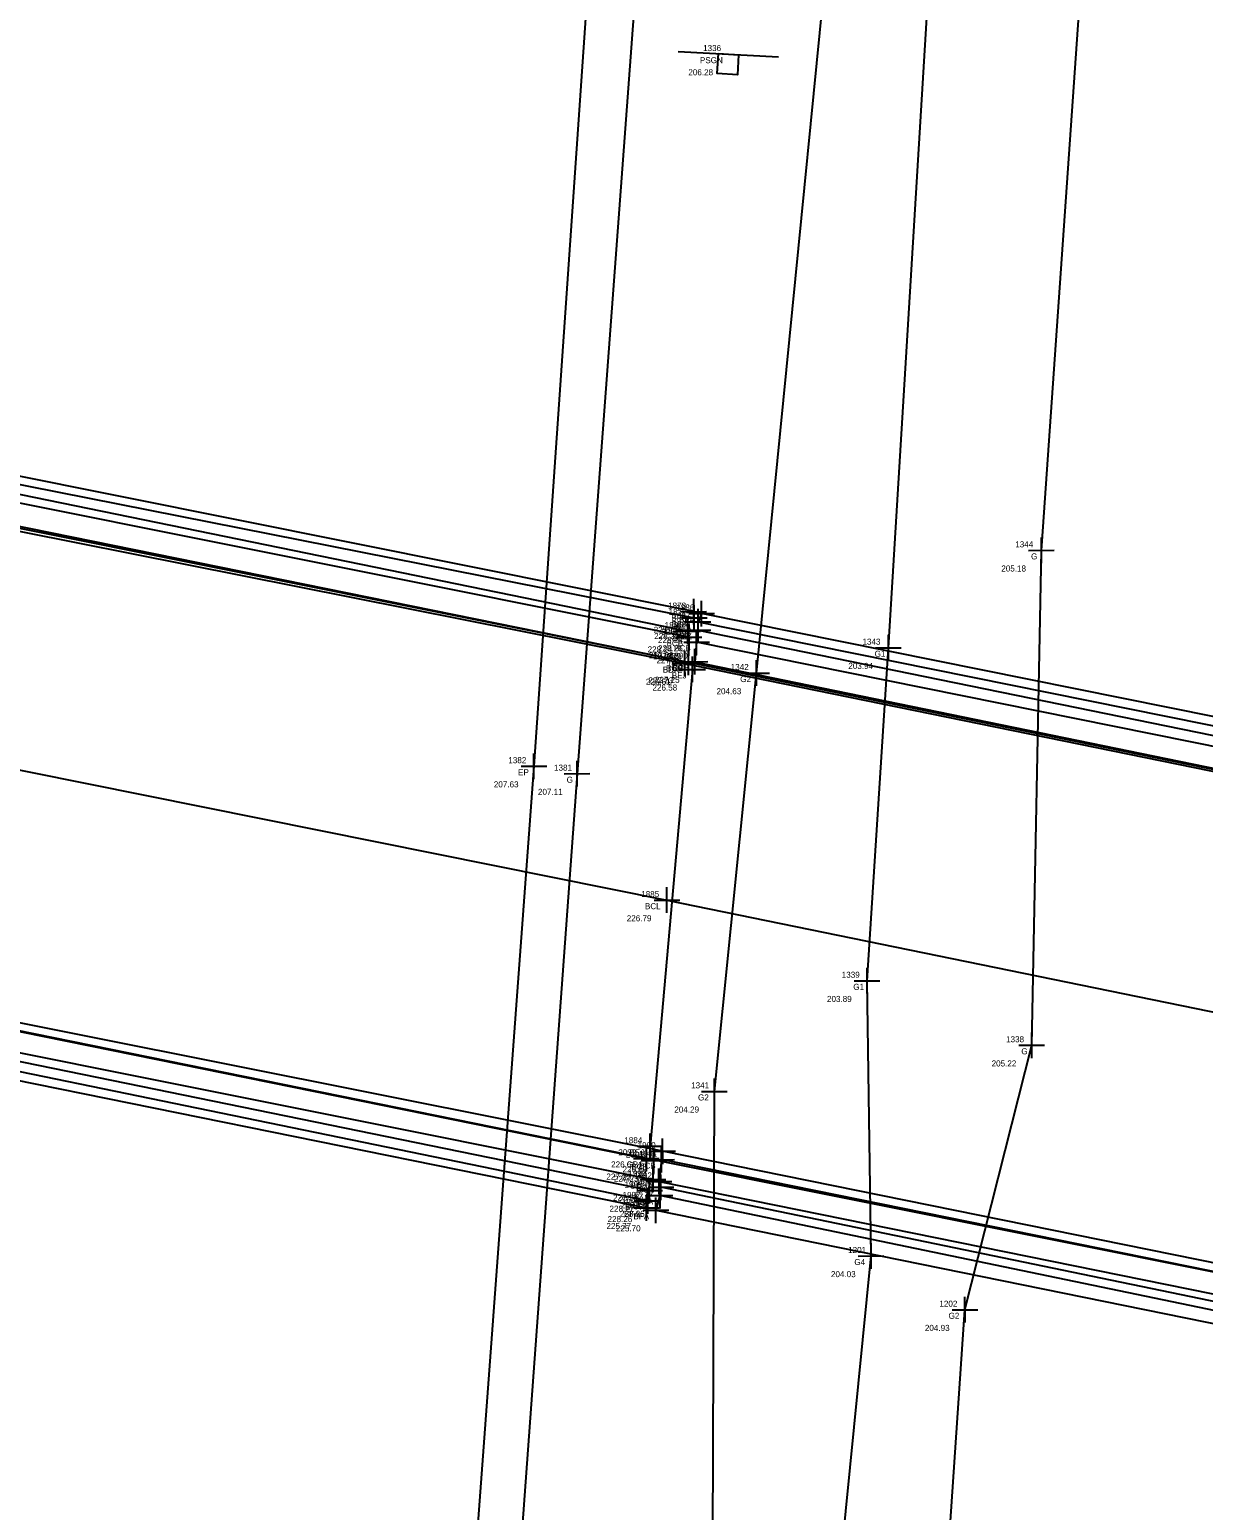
# Model space of a CAD drawing. Extents: x 1158983 to 1160032, y 610902 to 611573.
# Drawn here: x 1159401 to 1159459.3, y 611227.2 to 611300.7 of the extents above; entities that cross this region are included whole.
import ezdxf

# ---------------------------------------------------------------- set-up
doc = ezdxf.new("R2010")
doc.units = 0
for name, color, linetype in [('Default', 7, 'Continuous'), ('S_Bridge_Centerline', 7, 'Continuous'), ('S_Bridge_Curb', 7, 'Continuous'), ('S_Bridge_Deck', 7, 'Continuous'), ('S_Bridge_ExpansionJoint', 7, 'Continuous'), ('S_Bridge_Fascia', 7, 'Continuous'), ('S_Field_Code', 7, 'Continuous'), ('S_Ground_Elevation', 7, 'Continuous'), ('S_Guardrail_Beam', 7, 'Continuous'), ('S_Misc_MiscFeature', 7, 'Continuous'), ('S_Point_Elevation', 7, 'Continuous'), ('S_Point_Name', 7, 'Continuous'), ('S_Roadway_Edge_Pavement', 7, 'Continuous'), ('S_Survey_Shot', 7, 'Continuous'), ('S_Traffic_Sign_SinglePost', 7, 'Continuous')]:
    doc.layers.add(name, color=color, linetype=linetype)

msp = doc.modelspace()

# ---------------------------------------------------------------- linework, layer by layer
at = {"layer": 'Default'}
msp.add_line((1159435.703, 611299.476), (1159435.703, 611299.476), dxfattribs=at)
at = {"layer": 'S_Bridge_Centerline'}
msp.add_lwpolyline([(1159333.27, 611277.49), (1159375.085, 611269.079), (1159432.648, 611257.515), (1159502.769, 611243.159), (1159572.889, 611228.86), (1159630.259, 611216.999), (1159672.294, 611208.379)], dxfattribs=at)
at = {"layer": 'S_Bridge_Curb'}
for points in [[(1159376.749, 611281.964), (1159376.649, 611280.913), (1159433.724, 611269.316), (1159433.747, 611270.559)], [(1159434.12, 611270.309), (1159434.043, 611269.342), (1159503.64, 611255.058), (1159503.943, 611256.229)], [(1159431.968, 611243.66), (1159432.006, 611244.597), (1159374.882, 611256.199), (1159374.713, 611255.117)], [(1159502.019, 611229.4), (1159502.097, 611230.494), (1159432.384, 611244.643), (1159432.259, 611243.563)]]:
    msp.add_lwpolyline(points, close=True, dxfattribs=at)
at = {"layer": 'S_Bridge_Deck'}
msp.add_lwpolyline([(1159333.801, 611289.348), (1159375.965, 611280.699), (1159433.546, 611269.247), (1159503.551, 611254.972), (1159573.652, 611240.691), (1159630.945, 611229.008), (1159674.004, 611220.503), (1159672.341, 611196.28), (1159630.068, 611204.797), (1159572.75, 611216.514), (1159502.493, 611230.859), (1159432.439, 611245.062), (1159375.072, 611256.503), (1159331.888, 611265.329)], close=True, dxfattribs=at)
at = {"layer": 'S_Bridge_ExpansionJoint'}
msp.add_lwpolyline([(1159433.923, 611268.959), (1159431.823, 611245.308)], dxfattribs=at)
at = {"layer": 'S_Bridge_Fascia'}
for points in [[(1159377.015, 611283.251), (1159376.893, 611282.801), (1159434.008, 611271.511), (1159433.985, 611271.823)], [(1159434.373, 611271.73), (1159434.201, 611271.323), (1159503.969, 611257.243), (1159503.98, 611257.715)], [(1159431.641, 611242.253), (1159431.696, 611242.594), (1159374.735, 611254.312), (1159374.563, 611253.824)], [(1159501.804, 611227.968), (1159501.921, 611228.418), (1159432.308, 611242.862), (1159432.108, 611242.134)]]:
    msp.add_lwpolyline(points, close=True, dxfattribs=at)
at = {"layer": 'S_Ground_Elevation'}
for points in [[(1159454.139, 611570.997), (1159458.202, 611562.09), (1159457.609, 611547.211), (1159454.619, 611542.487), (1159450.49, 611533.823), (1159446.117, 611504.156), (1159442.895, 611458.608), (1159439.042, 611406.131), (1159435.384, 611353.576), (1159431.022, 611301.793), (1159428.193, 611263.786), (1159425.306, 611224.13), (1159422.825, 611193.921)], [(1159442.58, 611253.515), (1159443.638, 611270.034), (1159446.663, 611319.797), (1159445.969, 611361.1), (1159452.096, 611434.206), (1159455.542, 611485.465), (1159457.112, 611517.478), (1159459.746, 611531.666), (1159467.247, 611556.821), (1159464.351, 611565.449)], [(1159450.746, 611250.316), (1159451.228, 611274.864), (1159454.464, 611321.083), (1159460.98, 611368.506), (1159466.572, 611431.188), (1159472.814, 611485.778), (1159480.719, 611532.131), (1159483.428, 611564.473)], [(1159435.008, 611248.029), (1159437.102, 611268.779), (1159442.169, 611320.104)], [(1159442.777, 611239.865), (1159442.58, 611253.515)], [(1159447.437, 611237.199), (1159450.746, 611250.316)], [(1159434.908, 611221.492), (1159435.008, 611248.029)], [(1159548.979, 611025.788), (1159542.436, 611014.266), (1159539.927, 611011.357), (1159531.238, 611011.839), (1159506.951, 611012.56), (1159474.729, 611015.393), (1159451.448, 611016.781), (1159439.176, 611019.336), (1159436.035, 611022.533), (1159431.749, 611036.179), (1159430.572, 611089.92), (1159433.994, 611135.997), (1159437.548, 611187.051), (1159442.777, 611239.865)], [(1159563.258, 611229.802), (1159560.327, 611199.972), (1159558.111, 611173.246), (1159552.181, 611112.175), (1159547.04, 611094.195), (1159543.95, 611063.057), (1159534.181, 611016.708), (1159531.65, 611015.253), (1159507.988, 611014.741), (1159475.963, 611018.062), (1159451.464, 611020.697), (1159444.921, 611021.818), (1159442.672, 611026.506), (1159440.129, 611032.942), (1159436.622, 611046.038), (1159436.543, 611063.181), (1159435.008, 611090.376), (1159437.46, 611138.138), (1159443.944, 611185.758), (1159447.437, 611237.199)]]:
    msp.add_lwpolyline(points, dxfattribs=at)
at = {"layer": 'S_Guardrail_Beam'}
for p, q in [((1159375.839, 611280.908), (1159433.724, 611269.316)), ((1159433.724, 611269.316), (1159503.64, 611255.058))]:
    msp.add_line(p, q, dxfattribs=at)
msp.add_lwpolyline([(1159962.355, 611128.723), (1159954.927, 611131.331), (1159940.804, 611136.335), (1159922.846, 611140.981), (1159878.137, 611150.269), (1159824.181, 611161.329), (1159771.192, 611171.967), (1159724.558, 611182.82), (1159696.585, 611190.71), (1159683.564, 611193.82), (1159671.877, 611196.264), (1159629.625, 611204.61), (1159571.633, 611216.492), (1159501.577, 611230.682), (1159431.638, 611244.705), (1159374.182, 611256.374), (1159332.105, 611265.121)], dxfattribs=at)
at = {"layer": 'S_Misc_MiscFeature'}
for points in [[(1159376.941, 611282.479), (1159433.683, 611270.853)], [(1159434.199, 611270.905), (1159503.923, 611256.66)], [(1159431.791, 611243.111), (1159374.79, 611254.764)], [(1159501.916, 611228.898), (1159432.353, 611243.274)]]:
    msp.add_lwpolyline(points, dxfattribs=at)
at = {"layer": 'S_Roadway_Edge_Pavement'}
msp.add_lwpolyline([(1159451.831, 611570.814), (1159453.615, 611550.243), (1159453.735, 611546.55), (1159452.377, 611543.751), (1159448.762, 611533.854), (1159446.196, 611521.649), (1159443.913, 611504.847), (1159440.366, 611457.527), (1159436.414, 611406.688), (1159432.596, 611353.772), (1159428.66, 611301.968), (1159426.055, 611264.157), (1159423.109, 611224.366), (1159421.227, 611195.325), (1159419.39, 611189.09)], dxfattribs=at)
at = {"layer": 'S_Survey_Shot'}
for p, q in [((1159450.592, 611274.863), (1159451.864, 611274.866)), ((1159451.229, 611274.228), (1159451.227, 611275.501)), ((1159451.228, 611274.864), (1159451.228, 611274.864)), ((1159433.986, 611271.187), (1159433.984, 611272.459)), ((1159434.009, 611270.875), (1159434.006, 611272.148)), ((1159434.202, 611270.687), (1159434.199, 611271.96)), ((1159434.374, 611271.093), (1159434.371, 611272.366)), ((1159433.349, 611271.822), (1159434.621, 611271.824)), ((1159433.371, 611271.51), (1159434.644, 611271.513)), ((1159433.564, 611271.322), (1159434.837, 611271.325)), ((1159433.685, 611270.217), (1159433.682, 611271.49)), ((1159433.737, 611271.728), (1159435.009, 611271.731)), ((1159433.748, 611269.922), (1159433.745, 611271.195)), ((1159433.985, 611271.823), (1159433.985, 611271.823)), ((1159434.008, 611271.511), (1159434.008, 611271.511)), ((1159434.201, 611270.269), (1159434.198, 611271.541)), ((1159434.201, 611271.323), (1159434.201, 611271.323)), ((1159434.373, 611271.73), (1159434.373, 611271.73)), ((1159433.047, 611270.852), (1159434.32, 611270.855)), ((1159433.11, 611270.557), (1159434.383, 611270.56)), ((1159433.563, 611270.903), (1159434.836, 611270.906)), ((1159433.683, 611270.853), (1159433.683, 611270.853)), ((1159433.747, 611270.559), (1159433.747, 611270.559)), ((1159434.122, 611269.672), (1159434.119, 611270.945)), ((1159434.199, 611270.905), (1159434.199, 611270.905)), ((1159443.639, 611269.398), (1159443.636, 611270.671)), ((1159433.484, 611270.307), (1159434.757, 611270.31)), ((1159433.547, 611268.611), (1159433.545, 611269.883)), ((1159433.726, 611268.679), (1159433.723, 611269.952)), ((1159433.726, 611268.679), (1159433.723, 611269.952)), ((1159434.044, 611268.706), (1159434.041, 611269.978)), ((1159434.12, 611270.309), (1159434.12, 611270.309)), ((1159443.002, 611270.033), (1159444.274, 611270.036)), ((1159443.638, 611270.034), (1159443.638, 611270.034)), ((1159432.91, 611269.245), (1159434.182, 611269.248)), ((1159433.088, 611269.314), (1159434.36, 611269.317)), ((1159433.088, 611269.314), (1159434.36, 611269.317)), ((1159433.287, 611268.958), (1159434.559, 611268.961)), ((1159433.406, 611269.341), (1159434.679, 611269.343)), ((1159433.546, 611269.247), (1159433.546, 611269.247)), ((1159433.724, 611269.316), (1159433.724, 611269.316)), ((1159433.724, 611269.316), (1159433.724, 611269.316)), ((1159433.924, 611268.323), (1159433.922, 611269.596)), ((1159433.923, 611268.959), (1159433.923, 611268.959)), ((1159434.043, 611269.342), (1159434.043, 611269.342)), ((1159437.103, 611268.143), (1159437.1, 611269.415)), ((1159436.466, 611268.778), (1159437.738, 611268.78)), ((1159437.102, 611268.779), (1159437.102, 611268.779)), ((1159426.056, 611263.521), (1159426.054, 611264.793)), ((1159425.419, 611264.156), (1159426.691, 611264.158)), ((1159426.055, 611264.157), (1159426.055, 611264.157)), ((1159428.195, 611263.15), (1159428.192, 611264.423)), ((1159427.557, 611263.785), (1159428.83, 611263.788)), ((1159428.193, 611263.786), (1159428.193, 611263.786)), ((1159432.649, 611256.878), (1159432.647, 611258.151)), ((1159432.012, 611257.513), (1159433.284, 611257.516)), ((1159432.648, 611257.515), (1159432.648, 611257.515)), ((1159442.581, 611252.879), (1159442.579, 611254.151)), ((1159441.944, 611253.513), (1159443.216, 611253.516)), ((1159442.58, 611253.515), (1159442.58, 611253.515)), ((1159450.748, 611249.68), (1159450.745, 611250.952)), ((1159450.11, 611250.315), (1159451.383, 611250.317)), ((1159450.746, 611250.316), (1159450.746, 611250.316)), ((1159435.009, 611247.393), (1159435.006, 611248.666)), ((1159434.372, 611248.028), (1159435.644, 611248.031)), ((1159435.008, 611248.029), (1159435.008, 611248.029)), ((1159431.824, 611244.672), (1159431.822, 611245.944)), ((1159432.441, 611244.426), (1159432.438, 611245.699)), ((1159431.187, 611245.307), (1159432.459, 611245.309)), ((1159431.639, 611244.069), (1159431.636, 611245.341)), ((1159431.803, 611245.061), (1159433.076, 611245.064)), ((1159431.823, 611245.308), (1159431.823, 611245.308)), ((1159432.007, 611243.961), (1159432.004, 611245.233)), ((1159432.386, 611244.007), (1159432.383, 611245.279)), ((1159432.439, 611245.062), (1159432.439, 611245.062)), ((1159431.002, 611244.704), (1159432.274, 611244.707)), ((1159431.37, 611244.596), (1159432.642, 611244.598)), ((1159431.638, 611244.705), (1159431.638, 611244.705)), ((1159431.748, 611244.642), (1159433.02, 611244.644)), ((1159431.97, 611243.024), (1159431.967, 611244.296)), ((1159432.006, 611244.597), (1159432.006, 611244.597)), ((1159432.261, 611242.927), (1159432.258, 611244.2)), ((1159432.384, 611244.643), (1159432.384, 611244.643)), ((1159431.332, 611243.659), (1159432.605, 611243.661)), ((1159431.623, 611243.562), (1159432.896, 611243.565)), ((1159431.717, 611243.273), (1159432.989, 611243.275)), ((1159431.793, 611242.475), (1159431.79, 611243.747)), ((1159431.968, 611243.66), (1159431.968, 611243.66)), ((1159432.259, 611243.563), (1159432.259, 611243.563)), ((1159432.31, 611242.226), (1159432.307, 611243.498)), ((1159432.354, 611242.638), (1159432.351, 611243.91)), ((1159432.353, 611243.274), (1159432.353, 611243.274)), ((1159431.06, 611242.593), (1159432.332, 611242.596)), ((1159431.155, 611243.11), (1159432.428, 611243.112)), ((1159431.642, 611241.617), (1159431.64, 611242.889)), ((1159431.672, 611242.86), (1159432.945, 611242.863)), ((1159431.698, 611241.958), (1159431.695, 611243.231)), ((1159431.696, 611242.594), (1159431.696, 611242.594)), ((1159431.791, 611243.111), (1159431.791, 611243.111)), ((1159432.11, 611241.498), (1159432.107, 611242.77)), ((1159432.308, 611242.862), (1159432.308, 611242.862)), ((1159431.005, 611242.252), (1159432.277, 611242.254)), ((1159431.472, 611242.133), (1159432.745, 611242.135)), ((1159431.641, 611242.253), (1159431.641, 611242.253)), ((1159432.108, 611242.134), (1159432.108, 611242.134)), ((1159442.779, 611239.229), (1159442.776, 611240.501)), ((1159442.141, 611239.864), (1159443.414, 611239.866)), ((1159442.777, 611239.865), (1159442.777, 611239.865)), ((1159447.438, 611236.563), (1159447.435, 611237.835)), ((1159446.801, 611237.197), (1159448.073, 611237.2)), ((1159447.437, 611237.199), (1159447.437, 611237.199))]:
    msp.add_line(p, q, dxfattribs=at)
at = {"layer": 'S_Traffic_Sign_SinglePost'}
msp.add_line((1159433.212, 611299.614), (1159438.194, 611299.337), dxfattribs=at)
msp.add_lwpolyline([(1159435.205, 611299.503), (1159436.201, 611299.448), (1159436.146, 611298.452), (1159435.149, 611298.507)], close=True, dxfattribs=at)

# ---------------------------------------------------------------- texts
at = {"layer": 'S_Field_Code'}
for s, p in [('PSGN', (1159434.288, 611299.026)), ('G', (1159450.713, 611274.414)), ('BFA', (1159432.868, 611271.373)), ('BFA', (1159432.891, 611271.061)), ('BFA', (1159433.084, 611270.873)), ('BFA', (1159433.256, 611271.28)), ('ZZ', (1159432.883, 611270.403)), ('ZZ', (1159433.399, 611270.455)), ('BCB', (1159432.632, 611270.109)), ('BCB', (1159433.006, 611269.859)), ('G1', (1159442.953, 611269.584)), ('BDK', (1159432.445, 611268.797)), ('BCB', (1159432.609, 611268.866)), ('GB', (1159432.909, 611268.866)), ('BCB', (1159432.928, 611268.892)), ('BEJ', (1159432.893, 611268.509)), ('G2', (1159436.287, 611268.329)), ('EP', (1159425.268, 611263.707)), ('G', (1159427.679, 611263.336)), ('BCL', (1159431.561, 611257.065)), ('G1', (1159441.895, 611253.065)), ('G', (1159450.231, 611249.866)), ('G2', (1159434.193, 611247.579)), ('BEJ', (1159430.793, 611244.858)), ('BDK', (1159431.339, 611244.612)), ('GB1', (1159430.653, 611244.255)), ('BCB', (1159430.891, 611244.147)), ('BCB', (1159431.269, 611244.193)), ('BCB', (1159430.853, 611243.21)), ('BCB', (1159431.144, 611243.113)), ('ZZ', (1159430.991, 611242.661)), ('BFA', (1159431.191, 611242.412)), ('ZZ', (1159431.552, 611242.824)), ('BFA', (1159430.524, 611241.803)), ('BFA', (1159430.579, 611242.144)), ('BFA', (1159430.991, 611241.684)), ('G4', (1159441.948, 611239.415)), ('G2', (1159446.622, 611236.749))]:
    msp.add_text(s, height=0.3, dxfattribs=at).set_placement(p)
at = {"layer": 'S_Point_Elevation'}
for s, p in [('206.28', (1159433.714, 611298.426)), ('205.18', (1159449.239, 611273.814)), ('225.75', (1159431.996, 611270.773)), ('228.20', (1159432.019, 611270.461)), ('228.24', (1159432.212, 611270.273)), ('225.90', (1159432.384, 611270.68)), ('228.24', (1159431.694, 611269.803)), ('227.23', (1159431.758, 611269.509)), ('228.26', (1159432.21, 611269.855)), ('227.30', (1159432.132, 611269.259)), ('203.94', (1159441.649, 611268.984)), ('226.61', (1159431.607, 611268.197)), ('227.23', (1159431.735, 611268.266)), ('227.23', (1159431.735, 611268.266)), ('227.25', (1159432.054, 611268.292)), ('226.58', (1159431.934, 611267.909)), ('204.63', (1159435.113, 611267.729)), ('207.63', (1159424.066, 611263.107)), ('207.11', (1159426.254, 611262.736)), ('226.79', (1159430.659, 611256.465)), ('203.89', (1159440.591, 611252.465)), ('205.22', (1159448.757, 611249.266)), ('204.29', (1159433.019, 611246.979)), ('226.61', (1159429.884, 611244.258)), ('226.60', (1159430.451, 611244.012)), ('227.25', (1159429.649, 611243.655)), ('227.23', (1159430.017, 611243.547)), ('227.22', (1159430.395, 611243.593)), ('227.29', (1159429.979, 611242.61)), ('227.29', (1159430.27, 611242.513)), ('228.28', (1159430.364, 611242.224)), ('228.26', (1159429.707, 611241.544)), ('228.27', (1159429.803, 611242.061)), ('228.26', (1159430.319, 611241.812)), ('225.77', (1159429.652, 611241.203)), ('225.70', (1159430.119, 611241.084)), ('204.03', (1159440.788, 611238.815)), ('204.93', (1159445.448, 611236.149))]:
    msp.add_text(s, height=0.3, dxfattribs=at).set_placement(p)
at = {"layer": 'S_Point_Name'}
for s, p in [('1336', (1159434.446, 611299.626)), ('1344', (1159449.929, 611275.014)), ('1878', (1159432.712, 611271.973)), ('1877', (1159432.732, 611271.661)), ('1886', (1159433.116, 611271.88)), ('1881', (1159432.542, 611271.003)), ('1887', (1159432.928, 611271.473)), ('1888', (1159432.929, 611271.055)), ('1880', (1159432.478, 611270.709)), ('1889', (1159432.864, 611270.459)), ('1343', (1159442.353, 611270.184)), ('1879_1', (1159431.967, 611269.466)), ('1882', (1159432.275, 611269.397)), ('1879', (1159432.465, 611269.466)), ('1890', (1159432.789, 611269.492)), ('1883', (1159432.652, 611269.109)), ('1342', (1159435.817, 611268.929)), ('1382', (1159424.784, 611264.307)), ('1381', (1159427.053, 611263.936)), ('1885', (1159431.377, 611257.665)), ('1339', (1159441.323, 611253.665)), ('1338', (1159449.475, 611250.466)), ('1341', (1159433.853, 611248.179)), ('1884', (1159430.538, 611245.458)), ('1990', (1159431.2, 611245.212)), ('2032', (1159430.239, 611244.855)), ('2000', (1159430.612, 611244.747)), ('1991', (1159431.272, 611244.793)), ('1999', (1159430.74, 611243.81)), ('1992', (1159431.017, 611243.713)), ('1998', (1159430.549, 611243.261)), ('1994', (1159431.052, 611243.012)), ('1993', (1159431.111, 611243.424)), ('1996', (1159430.413, 611242.403)), ('1997', (1159430.452, 611242.744)), ('1995', (1159430.866, 611242.284)), ('1201', (1159441.639, 611240.015)), ('1202', (1159446.168, 611237.349))]:
    msp.add_text(s, height=0.3, dxfattribs=at).set_placement(p)

doc.saveas('drawing.dxf')
